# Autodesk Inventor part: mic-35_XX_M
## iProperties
Shininess: 20.0
Length Units: 11269
Angle Units: 11279
Time Units: 11290
Mass Units: 11283
Length Display Precision: 2
Angle Display Precision: 2
Part Number: mic-35_XX_M
Material: Nichtrostender Stahl - 440C
Document SubType Name: Modellieren
Description: mic 35 Sensoren
Checked By: Alves
Created: 2005-08
Designer: Ohle
Manufacturer: Standard
Standards Organization: Custom
Density: 0.0
Volumn: 0.0
Area: 0.0
PropertySet Name: Model Information
Control State: 0
Master: False
Checked Out: False
Last Check In By: Kramp
Last Check In Date: 2005-08-09
BESTELLNUMMER: mic-35/XX/M
ME: ST
Title: mic Sensoren
Author: Ohle
Comments: keine Bemerkung
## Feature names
1. Grundkörper [Revolution]
2. Bohrung1 [Hole]
3. Pole [Extrusion]
4. Abrundung Pole [Fillet]
5. Verdrehsicherung [Extrusion]
